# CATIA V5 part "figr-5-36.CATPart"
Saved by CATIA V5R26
Part number: Part1
Bounding box of the stored display mesh (mm): x -80 to 80, y -60 to 60, z 0 to 120
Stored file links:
  D:\_Deepak\CATIA\CATIA V5-6R2016_Deepak\Resources\Part files\Partfiles\c05_catia_v5_6r2016_prt\figr-5-36.CATPart
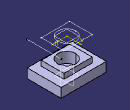
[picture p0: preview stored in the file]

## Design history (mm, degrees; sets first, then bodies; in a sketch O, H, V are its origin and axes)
Set1
  Plane1: type Offset, RefPlane xy-plane, Offset 120
Body1 (main body)
  Sketch1 on xy-plane, origin (0, 0, 0), H (1, 0, 0), V (0, 1, 0)
    line L1 (80, 60) -> (80, -60)
    line L2 (80, -60) -> (-80, -60)
    line L3 (-80, -60) -> (-80, 60)
    line L4 (-80, 60) -> (80, 60)
    circle A1 centre (0, 0) radius 31.6228
    line L5 (50, 40) -> (50, -40)
    line L6 (50, -40) -> (-50, -40)
    line L7 (-50, -40) -> (-50, 40)
    line L8 (-50, 40) -> (50, 40)
    vertical: L1 V, L3 V, L5 V, L7 V
    horizontal: L2 H, L4 H, L6 H, L8 H
    equidistance: L1 L3 O, L2 L4 O, L5 L7 O, L6 L8 O
  MultiPad1: profile Sketch1, domains (length 51; length 33; length 14)
  Sketch2 on Plane1, origin (0, 0, 120), H (1, 0, 0), V (0, 1, 0)
    projected line E1 (50, 40) -> (-50, 40) from edge [face of MultiPad1 | face of MultiPad1]
    projected line E2 (-50, 40) -> (-50, -40) from edge [face of MultiPad1 | face of MultiPad1]
    projected line E3 (-50, -40) -> (50, -40) from edge [face of MultiPad1 | face of MultiPad1]
    projected line E4 (50, -40) -> (50, 40) from edge [face of MultiPad1 | face of MultiPad1]
    projected circle E5 centre (0, 0) radius 31.6228 from edge [face of MultiPad1 | face of MultiPad1]
    projected line E6 (80, -60) -> (80, 60) from edge [face of MultiPad1 | face of MultiPad1]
